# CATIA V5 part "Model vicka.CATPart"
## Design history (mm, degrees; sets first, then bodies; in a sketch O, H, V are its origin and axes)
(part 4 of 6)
    projected arc E6 centre (-2.5848, 1.1233) radius 51.9999 from (-41.5221, 35.5889) to (-51.4432, 18.9237) ccw from edge [face of Fillet16 | face of Pad13]
    line L1 (-57.9293, -19.8837) -> (-56.7487, -23.9144)
    length L1 = 4.2
    tangency: L1 E1
  Slot3: profile Sketch84, centre curve Sketch85
  Sketch86 on face of Slot3, origin (0, -14.9615, 15.7588), H (1, 0, 0), V (0, 0.7252, 0.6885)
    line L1 (-0.7, -58.186) -> (-0.7, -61.911)
    reference intersected line E1 (1.6, 68.0393) -> (1.6, -68.0393) from face of Pad32
    projected line E2 (1.6, -57.611) -> (-2.4, -58.611) from edge [face of Slot3 | face of Slot3]
    projected line E3 (1.6, -57.611) -> (-0.7, -58.186) from edge [face of Slot3 | face of Slot3]
    point P3 (1.6, -57.611)
    projected line E4 (1.6, -61.911) -> (1.6, -57.611) from edge [face of Pad32 | face of Slot3]
    point P5 (1.6, -61.911)
    point P6 (1.6, -57.611)
    projected line E5 (-2.4, -61.911) -> (1.6, -61.911) from edge [face of Slot3 | face of Slot3]
    projected line E6 (-0.7, -61.911) -> (1.6, -61.911) from edge [face of Slot3 | face of Slot3]
    point P8 (1.6, -61.911)
    distance E1 L1 = 2.3
    vertical: L1 V
    coincidence: P3 P6, P5 P8
  Sketch87 on face of Pad32, origin (1.6, 0, 0), H (0, 1, 0), V (0, 0, 1)
    projected arc E1 centre (-17.5753, -8.1503) radius 42.0001 from (-56.5286, -23.8555) to (-52.2283, -31.8816) ccw from edge [face of Fillet16 | face of Chamfer13]
    projected arc E2 centre (-17.6227, -8.0775) radius 42.0001 from (-52.2266, -31.8805) to (-45.9223, -39.112) ccw from edge [face of Fillet16 | end face of Pocket10]
    projected arc E3 centre (-17.6227, -8.0775) radius 42.0001 from (-52.1953, -31.9259) to (-45.9223, -39.112) ccw from edge [face of Fillet16 | end face of Pocket10]
    line L1 (-52.2283, -31.8816) -> (-52.1953, -31.9259)
    point P5 (-52.1953, -31.9259)
    length L1 = 0.0552
    coincidence: P5 E2
  Slot4: profile Sketch86, centre curve Sketch87
  Sketch88 on face of Slot3, origin (0, 5.9901, 23.455), H (1, 0, 0), V (0, -0.9689, 0.2474)
    projected line E1 (-2.4, 53.3276) -> (1.6, 53.3276) from edge [face of Slot3 | face of Slot3]
    projected line E2 (-2.4, 50.0276) -> (-2.4, 53.3276) from edge [face of Slot3 | face of Slot3]
    projected line E3 (1.6, 49.0276) -> (-2.4, 50.0276) from edge [face of Slot3 | face of Slot3]
    projected line E4 (1.6, 53.3276) -> (1.6, 49.0276) from edge [face of Slot3 | face of Pad32]
  Sketch89 on face of Pad32, origin (1.6, 0, 0), H (0, 1, 0), V (0, 0, 1)
    projected arc E1 centre (-2.5799, 1.1183) radius 51.507 from (-39.4324, 37.1026) to (-41.129, 35.2788) ccw from edge [face of Pad17 from Sketch31.A1 | face of Chamfer24]
    offset arc E2 centre (-2.5799, 1.1183) radius 52.007 from (-39.7901, 37.4519) to (-41.5032, 35.6104) ccw from edge [face of Pad17 from Sketch31.A1 | face of Chamfer24]
  Slot5: profile Sketch88, centre curve Sketch89
  Sketch90 on face of Slot5, origin (0, 7.0774, 23.0092), H (1, 0, 0), V (0, -0.9558, 0.294)
    projected line E1 (1.6, 49.0459) -> (1.6, 53.3459) from edge [face of Pad32 | face of Slot5]
    line L1 (1.6, 53.3459) -> (-6.4, 53.3459)
    point P3 (-6.4, 53.3459)
    line L2 (1.6, 49.0459) -> (-6.4, 53.3459)
    point P4 (-6.4, 53.3459)
    length L1 = 8
    horizontal: L1 H
    coincidence: P4 L1, L2 P3, P3 P4
  Sketch91 on face of Pad32, origin (1.6, 0, 0), H (0, 1, 0), V (0, 0, 1)
    projected arc E1 centre (-2.5829, 1.1221) radius 55.5117 from (-39.111, 42.9222) to (-42.5969, 39.5984) ccw from edge [face of Pad16 from Sketch30.E12 | end face of Pad17]
    line L1 (-42.5969, 39.5984) -> (-43.569, 38.5875)
    point P3 (-43.569, 38.5875)
    reference projected line E2 (-39.801, 37.4285) -> (-43.911, 38.6927) from edge [face of Pad32 | face of Slot5]
    distance P3 E2 = 0
    tangency: L1 E1
  Slot6: profile Sketch90, centre curve Sketch91
  Sketch92 on face of Pad32, origin (1.6, 0, 0), H (0, 1, 0), V (0, 0, 1)
    projected arc E1 centre (-2.5799, 1.1183) radius 51.507 from (-34.6189, 41.4479) to (-36.525, 39.8572) ccw from edge [face of Pad17 from Sketch31.A1 | face of Chamfer16]
    point P2 (-36.525, 39.8572)
    projected line E2 (-34.3922, 41.6269) -> (-34.6189, 41.4479) from edge [face of Pad12 | face of Chamfer16]
    projected line E4 (-32.9726, 42.7142) -> (-33.1688, 42.5588) from edge [face of Pad12 from Sketch20.L1 | face of Fillet15]
    projected arc E6 centre (-31.5752, 59.6552) radius 16.4993 from (-31.8705, 43.1586) to (-18.0387, 50.2219) ccw from edge [face of Pad12 from Sketch20.E32 | face of Fillet15]
    projected arc E7 centre (-8.752, 43.4382) radius 11.5005 from (-8.0778, 54.9189) to (-18.0387, 50.2219) ccw from edge [face of Pad12 from Sketch20.A1 | face of Fillet15]
    projected line E8 (13.3045, 53.6631) -> (-8.0778, 54.9189) from edge [face of Pad12 from Sketch20.E34 | face of Fillet15]
    projected arc E9 centre (7.4339, 25.3633) radius 28.9024 from (16.8502, 52.6887) to (13.3045, 53.6631) ccw from edge [face of Pad12 from Sketch20.E36 | face of Fillet15]
    projected arc E10 centre (7.4339, 25.3633) radius 28.9024 from (26.0505, 47.4714) to (20.4962, 51.1455) ccw from edge [face of Pad12 from Sketch20.E36 | face of Fillet15]
    projected arc E11 centre (7.4339, 25.3633) radius 28.9024 from (20.4962, 51.1455) to (18.2767, 52.1547) ccw from edge [face of Pad12 from Sketch20.E36 | face of Fillet15]
    projected arc E12 centre (40.4358, 56.1497) radius 16.6459 from (26.309, 47.3451) to (29.0781, 43.9805) ccw from edge [face of Chamfer6 | face of Fillet15]
    projected arc E13 centre (40.4358, 56.1497) radius 16.6459 from (27.5108, 45.6601) to (29.0781, 43.9805) ccw from edge [face of Chamfer6 | face of Fillet15]
    line L1 (26.0505, 47.4714) -> (27.5108, 45.6601)
    point P25 (27.5108, 45.6601)
    line L2 (18.2767, 52.1547) -> (16.8502, 52.6887)
    length L1 = 2.3266
    coincidence: P25 E12
  Plane6: type Normal, Curve Sketch92, RefPoint Sketch92.P2, Ratio 0
  Sketch93 on Plane6, origin (0, -0.9051, -0.7931), H (1, 0, 0), V (0, -0.659, 0.7521)
    line L1 (1.6, 54.0775) -> (1.6, 58.3775)
    line L2 (1.6, 58.3775) -> (-2.4, 58.3775)
    line L3 (-2.4, 58.3775) -> (-2.4, 55.0775)
    line L4 (-2.4, 55.0775) -> (1.6, 54.0775)
    reference projected line E1 (1.6, 52.57) -> (1.6, 60.7584) from edge [face of Pad32 | face of Pad10]
    reference projected line E2 (1.6, 58.3775) -> (-6.4, 58.3775) from edge [face of Slot6 | face of Slot6]
    distance L1 E1 = 0
    length L1 = 4.3
    length L3 = 3.3
    length L2 = 4
    distance L2 E2 = 0
    vertical: L1 V, L3 V
    horizontal: L2 H
  Slot7: profile Sketch93, centre curve Sketch92
  Chamfer28: length 4.9, angle 10, on edge [face of Slot5 | face of Slot5]
  Sketch94 on face of Pad32, origin (1.6, 0, 0), H (0, 1, 0), V (0, 0, 1)
    projected line E1 (-39.2656, 42.9849) -> (-39.3781, 43.1132) from edge [face of Slot7 | face of Pad32]
    projected line E2 (-39.2656, 42.9849) -> (-39.4426, 43.0566) from edge [face of Pad32 | face of Slot6]
    line L1 (-39.4426, 43.0566) -> (-39.3781, 43.1132)
    point P5 (-39.3781, 43.1132)
    length L1 = 0.0858
    coincidence: P5 E1
  Pocket31: profile Sketch94, direction (-1, 0, 0), length 4
  Sketch95 on face of Pad32, origin (1.6, 0, 0), H (0, 1, 0), V (0, 0, 1)
    projected arc E1 centre (-2.5799, 1.1183) radius 55.8361 from (-37.3069, 44.8414) to (-39.3781, 43.1132) ccw from edge [face of Pad32 | face of Slot7]
    projected arc E2 centre (-2.5799, 1.1183) radius 55.8361 from (-37.8798, 44.3802) to (-38.8031, 43.6101) ccw from edge [face of Pad32 | face of Slot7]
    point P2 (-39.3781, 43.1132)
    line L1 (-38.8031, 43.6101) -> (-37.4611, 39.7118)
    point P3 (-38.8184, 43.6551)
    point P4 (-37.4611, 39.7118)
    line L2 (-36.3174, 39.8416) -> (-37.8798, 44.3802)
    point P5 (-36.3174, 39.8416)
    point P6 (-37.6765, 44.2587)
    point P7 (-38.8031, 43.6101)
    point P8 (-38.8031, 43.6101)
    line L3 (-36.3174, 39.8416) -> (-36.215, 39.544)
    line L4 (-36.215, 39.544) -> (-37.4611, 39.7118)
    point P10 (-37.8798, 44.3802)
    point P11 (-37.8798, 44.3802)
    reference projected point E3 (-36.868, 40.2487) from vertex [face of Slot6 | face of Slot7 | face of Pad32]
    distance P3 E1 = 0.0442
    distance P3 P4 = 4.1703
    length L1 = 4.1228
    angle L1 L2 = 0
    distance P6 P7 = 1.3
    length L3 = 0.3147
    length L4 = 1.2574
    distance P5 P6 = 4.6215
    distance L1 P2 = 0.7054
    length L2 = 4.8
    distance P4 E3 = 0.8
    coincidence: L1 P7, E1 P8, L2 P10, E1 P11, P7 P8, P10 P11
    parallelism: L3 L2
  Pad33: profile Sketch95, direction (-1, 0, 0), up to the existing solid (limit type 2)
  Fillet36: radius 0.5, on edge [face of Pocket31 | face of Slot6]
  Fillet37: radius 0.5, on edge [face of Pad33 from Sketch95.L1 | face of Slot6]
  Sketch96 on face of Pad33, origin (1.6, 0, 0), H (0, 1, 0), V (0, 0, 1)
    projected arc E1 centre (-2.5799, 1.1183) radius 55.8578 from (-43.911, 38.6927) to (-45.6792, 36.6506) ccw from edge [face of Pad33 | face of Slot5]
    projected arc E2 centre (-2.5799, 1.1183) radius 55.8578 from (-43.911, 38.6927) to (-44.1709, 38.4048) ccw from edge [face of Pad33 | face of Slot5]
    point P1 (-43.911, 38.6927)
    projected line E3 (-42.9389, 39.7036) -> (-43.911, 38.6927) from edge [face of Pad33 | face of Slot6]
    projected line E4 (-43.2784, 39.3505) -> (-43.911, 38.6927) from edge [face of Pad33 | face of Slot6]
    point P4 (-43.911, 38.6927)
    projected line E5 (-40.3201, 36.8887) -> (-42.7571, 34.3543) from edge [face of Slot6 | face of Pad33]
    projected line E6 (-40.4271, 36.7774) -> (-41.3286, 35.8399) from edge [face of Slot6 | face of Pad33]
    point P7 (-45.0411, 37.4107)
    line L1 (-40.4271, 36.7774) -> (-43.2784, 39.3505)
    point P8 (-43.2784, 39.3505)
    point P9 (-40.4257, 36.7762)
    reference projected point E7 (-41.8454, 38.0573) from vertex [face of Slot5 | face of Chamfer28 | face of Slot6]
    line L2 (-41.3286, 35.8399) -> (-44.1709, 38.4048)
    point P10 (-41.3286, 35.8399)
    point P11 (-44.1709, 38.4048)
    point P12 (-40.4271, 36.7774)
    point P13 (-40.4271, 36.7774)
    distance E7 L1 = 0
    distance L1 L2 = 1.3
    length L2 = 3.8285
    distance P9 P8 = 3.8425
    coincidence: P8 E3, P10 E5, P11 E1, L1 P12, E5 P13, P1 P4, P12 P13
  Pad34: profile Sketch96, direction (-1, 0, 0), length 8
  Fillet38: radius 0.5, on edge [face of Slot6 | face of Slot6] (x3); edge [face of Slot6 | face of Pad34 from Sketch96.L1]; edge [face of Pad34 from Sketch96.L1 | face of Slot6]
  Sketch97 on face of Pad34, origin (1.6, 0, 0), H (0, 1, 0), V (0, 0, 1)
    projected arc E1 centre (32.0438, -10.8008) radius 27.8537 from (58.2467, -20.2473) to (59.3934, -16.076) ccw from edge [face of Chamfer3 | end face of Pad14]
    projected arc E2 centre (32.0438, -10.8008) radius 27.8537 from (58.6529, -19.0338) to (59.3934, -16.076) ccw from edge [face of Chamfer3 | end face of Pad14]
    point P2 (59.3934, -16.076)
    projected arc E3 centre (54.1383, -15.5258) radius 5.2838 from (59.3934, -16.076) to (58.8266, -13.0889) ccw from edge [face of Chamfer3 | end face of Pad14]
    point P3 (59.3934, -16.076)
    projected arc E4 centre (71.4411, -6.5318) radius 14.217 from (57.4963, -3.7635) to (58.8266, -13.0889) ccw from edge [face of Chamfer3 | end face of Pad14]
    projected arc E5 centre (44.449, -1.1758) radius 13.3015 from (57.4964, -3.7632) to (57.7347, -0.5287) ccw from edge [face of Chamfer3 | end face of Pad14]
    projected arc E6 centre (-26.1964, -18.2876) radius 85.7893 from (57.7347, -0.5287) to (33.9846, 42.8521) ccw from edge [face of Chamfer3 | end face of Pad14]
    line L1 (33.9846, 42.8521) -> (33.2896, 43.5711)
    point P11 (33.2896, 43.5711)
    reference projected arc E7 centre (40.4358, 56.1497) radius 12.3168 from (30.8763, 48.3831) to (32.0319, 47.1453) ccw from edge [face of Slot7 | face of Pad32]
    point P12 (58.6529, -19.0338)
    distance P11 E7 = 2.15
    length L1 = 1
    coincidence: P2 P3
  Plane7: type Normal, Curve Sketch97, RefPoint Sketch97.P12, Ratio 0
  Sketch98 on Plane7, origin (0, -0.2503, -0.8088), H (-1, 0, 0), V (0, -0.9553, 0.2956)
    line L1 (-1.6, -63.2013) -> (6.4, -63.2013)
    line L2 (6.4, -63.2013) -> (-1.6, -58.9013)
    line L3 (-1.6, -58.9013) -> (-1.6, -63.2013)
    reference intersected line E1 (-1.6, -71.42) -> (-1.6, 71.42) from face of Pad34
    distance L3 E1 = 0
    length L3 = 4.3
    length L1 = 8
    distance L1 H = 63.2013
    horizontal: L1 H
    vertical: L3 V
  Slot8: profile Sketch98, centre curve Sketch97
  Sketch99 on face of Slot7, origin (0, -6.3971, 5.9705), H (1, 0, 0), V (0, 0.6823, 0.7311)
    projected line E1 (1.6, 56.3219) -> (-2.4, 56.3219) from edge [face of Slot7 | face of Slot7]
    projected line E2 (1.6, 56.3219) -> (1.2703, 56.3219) from edge [face of Slot7 | face of Slot7]
    point P1 (1.6, 56.3219)
    projected line E3 (1.6, 53.76) -> (1.6, 56.3219) from edge [face of Pad34 | face of Slot7]
    point P4 (1.6, 56.3219)
    projected curve E4 from edge [face of Pocket14 from Sketch58.E5 | face of Slot7]
    line L1 (0.4039, 54.2321) -> (1.2703, 56.3219)
    point P7 (1.2703, 56.3219)
    reference projected line E5 (0.4039, 54.2321) -> (-0.314, 52.5004) from edge [face of Slot7 | face of Pocket16]
    angle L1 E5 = 180
    coincidence: P7 E1, P1 P4
  Pocket32: profile Sketch99, direction (0, 0.7311, -0.6823), length 3
  Sketch100 on face of Pad34, origin (1.6, 0, 0), H (0, 1, 0), V (0, 0, 1)
    projected line E1 (34.9087, 45.3925) -> (45.2512, 35.05) from edge [face of Pocket16 | face of Pad34]
    projected curve E2 from edge [face of Pocket14 from Sketch58.E5 | face of Pad34]
    projected curve E3 from edge [face of Pad34 | face of Pocket14 from Sketch58.E5]
    point P6 (33.7826, 45.5113)
    projected arc E4 centre (-26.1964, -18.2876) radius 87.3324 from (45.5459, 31.512) to (35.0808, 43.9383) ccw from edge [face of Slot8 | face of Pocket16]
    projected arc E5 centre (-26.1964, -18.2876) radius 87.3324 from (45.3346, 31.815) to (35.0808, 43.9383) ccw from edge [face of Slot8 | face of Pocket16]
    projected line E6 (34.3992, 44.6436) -> (35.0808, 43.9383) from edge [face of Slot8 | face of Pocket16]
    projected line E7 (33.6779, 45.6091) -> (34.2251, 45.0984) from edge [face of Pocket32 from Sketch99.E2 | face of Pocket16]
    projected line E8 (33.7826, 45.5113) -> (34.2251, 45.0984) from edge [face of Pocket32 from Sketch99.E2 | face of Pocket16]
    line L1 (34.3992, 44.6436) -> (34.2251, 45.0984)
    point P13 (34.3992, 44.6436)
    point P14 (45.3346, 31.815)
    point P15 (33.7826, 45.5113)
    length L1 = 0.487
    coincidence: P13 E6, E2 P14, E3 P15, P6 P15
  Pad35: profile Sketch100, direction (-1, 0, 0), up to the existing solid (limit type 2)
  Fill1: Boundary (edge [face of Pocket14 from Sketch58.E5 | face of Slot8]; edge [face of Slot8 | face of Pad35 from Sketch100.E2]; edge [face of Slot8 | face of Pocket16])
  Fill2: Boundary (edge [face of Pad35 from Sketch100.E3 | face of Pocket32]; edge [face of Pocket32 | face of Pocket16]; edge [face of Pocket32 | face of Pocket14 from Sketch58.E5])
  SewSurface1: SplitPlane Fill2
  SewSurface2: SplitPlane Fill1
  Sketch101 on face of Pad30, origin (-16.699, 4.8982, 4.8982), H (0.2815, 0.9596, 0), V (0.26, -0.0763, 0.9626)
  Sketch102 on face of Slot7, origin (0, -6.3971, 5.9705), H (1, 0, 0), V (0, 0.6823, 0.7311)
  Pocket33: profile Sketch102, direction (0, 0.7311, -0.6823), length 3.45
  Sketch103 on face of Pocket16, origin (-18.7311, 5.4943, 5.4943), H (0.2815, 0.9596, 0), V (0.26, -0.0763, 0.9626)
    projected line E1 (29.4824, 41.6823) -> (31.5877, 39.5448) from edge [face of Pocket16 | face of Pocket32 from Sketch99.E4]
    projected line E2 (29.4824, 41.6823) -> (28.1465, 40.3672) from edge [face of Pocket33 | face of Pocket16]
    projected line E3 (30.6493, 38.249) -> (33.3549, 40.6705) from edge [face of Slot8 | face of Pocket16]
    projected line E4 (31.5877, 39.5448) -> (33.211, 41.143) from edge [face of Pocket16 | end face of Pocket32]
    projected line E5 (33.3549, 40.6705) -> (33.211, 41.143) from edge [face of Pad35 from Sketch100.L1 | face of Pocket16]
    line L1 (30.6493, 38.249) -> (28.1465, 40.3672)
    point P11 (28.1465, 40.3672)
    length L1 = 3.2788
    coincidence: P11 E2
  Pocket34: profile Sketch103, direction (-0.9237, 0.2709, 0.2709), length 0.045
  Sketch104 on face of Pad35, origin (1.6, 0, 0), H (0, 1, 0), V (0, 0, 1)
    projected line E1 (34.2251, 45.0984) -> (34.3992, 44.6436) from edge [face of Pad35 from Sketch100.L1 | face of Pad35]
    line L1 (34.2251, 45.0984) -> (34.5351, 44.7902)
    line L2 (34.3992, 44.6436) -> (34.5351, 44.7902)
    angle L2 L1 = 92
    length L2 = 0.2
  Pocket35: profile Sketch104, direction (-1, 0, 0), length 1.045
  Sketch105 on face of Pad35, origin (1.6, 0, 0), H (0, 1, 0), V (0, 0, 1)
    projected line E1 (32.0319, 47.1453) -> (34.5541, 44.7913) from edge [face of Pocket33 | face of Pocket33]
    projected line E2 (34.2145, 45.1082) -> (34.5541, 44.7913) from edge [face of Pocket33 | face of Pocket33]
    point P2 (34.5541, 44.7913)
    projected line E3 (34.5541, 44.7913) -> (34.4078, 44.6346) from edge [face of Pocket33 | end face of Pocket33]
    point P3 (34.5541, 44.7913)
    projected line E4 (34.3992, 44.6436) -> (35.0808, 43.9383) from edge [face of Pad35 | face of Pad35]
    projected line E5 (34.3992, 44.6436) -> (34.4078, 44.6346) from edge [face of Pad35 | face of Pad35]
    line L1 (34.3992, 44.6436) -> (34.2145, 45.1082)
    point P7 (34.2145, 45.1082)
    length L1 = 0.5
    coincidence: P7 E1, P2 P3
  Pad36: profile Sketch105, direction (-1, 0, 0), up to the existing solid (limit type 2)
  Sketch106 on face of Pocket16, origin (-18.7311, 5.4943, 5.4943), H (0.2815, 0.9596, 0), V (0.26, -0.0763, 0.9626)
    line L1 (30.7758, 38.1148) -> (30.5655, 37.9079)
    point P1 (30.7758, 38.1148)
    line L2 (30.5655, 37.9079) -> (28.1465, 40.3672)
    point P3 (28.1465, 40.3672)
    point P4 (30.7758, 38.1148)
    projected line E1 (28.1465, 40.3672) -> (30.6493, 38.249) from edge [face of Pocket16 | face of Pocket34 from Sketch103.L1]
    point P5 (28.1465, 40.3672)
    projected line E2 (30.6525, 38.2519) -> (30.6493, 38.249) from edge [face of Pocket34 from Sketch103.E3 | face of Slot8]
    projected line E3 (30.6527, 38.2517) -> (30.7758, 38.1148) from edge [face of Slot8 | face of Pocket33]
    point P10 (30.7758, 38.1148)
    distance P1 P4 = 0
    distance P3 P5 = 0
    angle L1 L2 = 90
    length L1 = 0.295
    distance P1 P10 = 0
  Pocket36: profile Sketch106, direction (-0.9237, 0.2709, 0.2709), through (limit type 6)
  Draft4: Angle -3.5, Neutral face of Pocket16, PullDir face of Pocket16, SupportToDraft (end face of Pocket33; face of Pocket36 from Sketch106.L1)
  Fillet39: radius 3, on edge [face of Pocket33 | face of Slot8]
  Fillet40: radius 3, on edge [face of Pad36 from Sketch105.L1 | face of Pad35]
  Fillet41: radius 1, on edge [face of Pocket33 | face of Fillet40]
  Fillet42: radius 1.1, on edge [face of Pocket33 | face of Slot8]
  Fillet43: radius 0.75, on edge [face of Slot8 | face of Pocket36 from Sketch106.L1]
  Sketch107 on face of Pad36, origin (1.6, 0, 0), H (0, 1, 0), V (0, 0, 1)
    line L1 (33.2087, 46.047) -> (30.8894, 42.9692)
    line L2 (32.7188, 41.2429) -> (34.8949, 44.1306)
    projected line E1 (32.0319, 47.1453) -> (34.074, 45.2394) from edge [face of Pocket33 | face of Pad36]
    projected line E2 (33.2087, 46.047) -> (34.074, 45.2394) from edge [face of Pocket33 | face of Pad36]
    projected line E3 (29.4244, 44.3516) -> (32.0678, 41.8573) from edge [face of Pocket16 | face of Pocket36 from Sketch106.L2]
    projected line E4 (30.8894, 42.9692) -> (32.7188, 41.2429) from edge [face of Pocket16 | face of Pocket36 from Sketch106.L2]
    reference projected line E5 (32.5901, 32.7314) -> (38.0088, 38.1501) from Line1
    point P5 (32.7188, 41.2429)
    point P6 (30.8894, 42.9692)
    point P7 (33.2087, 46.047)
    projected arc E6 centre (33.3917, 44.5083) radius 1 from (34.2851, 44.9575) to (34.074, 45.2394) ccw from edge [face of Fillet41 | face of Pad36]
    projected arc E7 centre (36.9654, 46.3052) radius 3 from (34.2851, 44.9575) to (34.8083, 44.2202) ccw from edge [face of Pad36 | face of Fillet40]
    projected line E8 (34.8083, 44.2202) -> (35.0808, 43.9383) from edge [face of Pad35 | face of Pad36]
    projected line E9 (34.8083, 44.2202) -> (34.8949, 44.1306) from edge [face of Pad35 | face of Pad36]
    point P14 (34.8949, 44.1306)
    point P15 (34.8949, 44.1306)
    distance L1 L2 = 2.5
    angle L2 E5 = 8
    length L1 = 3.8538
    coincidence: E3 P5, E3 P6, E1 P7, L2 P14, E8 P15
  Pad37: profile Sketch107, direction (-1, 0, 0), up to the existing solid (limit type 2)
  Chamfer29: length 3.8, angle 26.2, on edge [face of Pad37 from Sketch107.E4 | face of Pad37]
  Sketch108 on face of Pocket16, origin (-18.7311, 5.4943, 5.4943), H (0.2815, 0.9596, 0), V (0.26, -0.0763, 0.9626)
    offset arc E1 centre (31.0473, 28.8138) radius 9.9633 from (30.7391, 18.8553) to (39.9051, 24.2523) ccw from edge [face of Pocket14 from Sketch58.E5 | face of Pocket16]
    offset arc E2 centre (31.0473, 28.8138) radius 9.9633 from (26.5278, 37.6931) to (30.7391, 18.8553) ccw from edge [face of Pocket15 | face of Pocket16]
    point P3 (26.5278, 37.6931)
    offset arc E3 centre (31.0473, 28.8138) radius 9.9633 from (28.2025, 38.3624) to (26.5278, 37.6931) ccw from edge [face of Pocket14 from Sketch58.E5 | face of Pocket16]
    point P6 (26.5278, 37.6931)
    arc A1 centre (31.0474, 28.8136) radius 9.9635 from (28.2025, 38.3624) to (29.7965, 38.6983) cw
    point P8 (29.228, 38.6096)
    arc A2 centre (31.0483, 28.8157) radius 9.9633 from (39.9051, 24.2523) to (40.5837, 25.9271) ccw
    point P10 (22.3411, 33.6585)
    point P11 (29.8518, 39.0314)
    projected line E4 (29.5646, 38.9363) -> (30.7209, 37.7499) from edge [face of Pad37 from Sketch107.E4 | face of Chamfer29]
    projected line E5 (29.5646, 38.9363) -> (29.7965, 38.6983) from edge [face of Pad37 from Sketch107.E4 | face of Chamfer29]
    point P12 (29.5646, 38.9363)
    projected arc E6 centre (31.0473, 28.8138) radius 12.9633 from (27.346, 41.2375) to (25.1669, 40.3667) ccw from edge [face of Pocket14 from Sketch58.E5 | face of Pocket16]
    point P14 (27.346, 41.2375)
    projected arc E7 centre (31.0473, 28.8138) radius 12.9633 from (25.1669, 40.3667) to (30.6462, 15.8567) ccw from edge [face of Pocket15 | face of Pocket16]
    projected arc E8 centre (31.0473, 28.8138) radius 12.9633 from (30.6462, 15.8567) to (42.5722, 22.8788) ccw from edge [face of Pocket14 from Sketch58.E5 | face of Pocket16]
    point P19 (42.5722, 22.8788)
    point P20 (29.7965, 38.6983)
    projected line E9 (28.1465, 40.3672) -> (29.559, 38.9311) from edge [face of Pocket16 | face of Pocket36 from Sketch106.L2]
    projected curve E10 from edge [face of Slot7 | face of Pocket16]
    projected curve E11 from edge [face of Slot8 | face of Pocket16]
    projected curve E12 from edge [face of Slot8 | face of Pocket16]
    point P25 (42.5722, 22.8788)
    point P27 (40.5837, 25.9271)
    projected line E13 (29.5646, 38.9363) -> (29.559, 38.9311) from edge [face of Pad37 from Sketch107.L1 | face of Pad37 from Sketch107.E4]
    point P28 (29.5646, 38.9363)
    radius A2 = 9.9633
    "Length" P25 P27 E11 = 3.6398
    radius A1 = 9.9635
    distance P20 P14 = 3.5288
    coincidence: P6 P3, A1 P8, P8 E3, A2 P10, P10 A1, P12 P28, P19 P25
  Pad38: profile Sketch108, direction (0.9237, -0.2709, -0.2709), length 10.2
  Sketch109 on zx-plane, origin (0, 0, 0), H (-1, 0, 0), V (0, 0, 1)
    line L1 (-1.6, 15) -> (-11.6, 15)
    line L2 (-11.6, 15) -> (-11.6, 45)
    line L3 (-11.6, 45) -> (-1.6, 45)
    line L4 (-1.6, 45) -> (-1.6, 15)
    reference projected line E1 (-1.6, -62.4295) -> (-1.6, 71.425) from edge [face of Pad1 from Sketch1.A1 | face of Pad37]
    distance L4 E1 = 0
    length L3 = 10
    length L2 = 30
    distance L1 H = 15
    horizontal: L1 H, L3 H
    vertical: L2 V, L4 V
  Pocket37: profile Sketch109, direction (0, -1, 0), through (limit type 6)
  Chamfer30: length 0.31, angle 85, on edge [face of Pocket14 from Sketch58.E5 | face of Slot7]
  Fillet44: radius 0.5, on edge [face of Chamfer30 | face of Slot7]; edge [face of Pad38 from Sketch108.E10 | face of Chamfer30]
  Fillet45: radius 1.1, on edge [face of Pad38 from Sketch108.E12 | face of Pad38 from Sketch108.E8]
  Sketch110 on face of Pad37, origin (1.6, 0, 0), H (0, 1, 0), V (0, 0, 1)
    line L1 (42.8242, 28.3998) -> (42.8242, 35.2204)
    point P1 (42.8242, 35.4644)
    line L2 (44.8242, 24.7293) -> (44.8242, 32.5359)
    projected arc E1 centre (42.6872, 26.7077) radius 1.0654 from (43.7295, 26.4869) to (43.5769, 27.2939) ccw from edge [face of Pad37 | face of Fillet45]
    point P2 (43.7295, 26.4869)
    point P3 (43.5769, 27.2939)
    projected arc E2 centre (-26.1964, -18.2876) radius 87.3324 from (59.2693, -0.3274) to (35.0808, 43.9383) ccw from edge [face of Pad37 | face of Slot8]
    projected arc E3 centre (-26.1964, -18.2876) radius 87.3324 from (44.8242, 32.5359) to (42.8242, 35.2204) ccw from edge [face of Pad37 | face of Slot8]
    projected arc E4 centre (-30.3056, -22.1814) radius 88.9182 from (43.5769, 27.2939) to (41.8242, 29.8159) ccw from edge [face of Pad37 | face of Pad38 from Sketch108.E12]
    projected arc E5 centre (-30.3056, -22.1814) radius 88.9182 from (43.5769, 27.2939) to (42.8242, 28.3998) ccw from edge [face of Pad37 | face of Pad38 from Sketch108.E12]
    point P6 (43.5769, 27.2939)
    point P7 (41.8242, 29.8159)
    projected arc E6 centre (-26.1964, -18.2876) radius 83.0324 from (54.9892, -0.8725) to (43.7295, 26.4869) ccw from edge [face of Slot8 | face of Pad37]
    projected arc E7 centre (-26.1964, -18.2876) radius 83.0324 from (44.8242, 24.7293) to (43.7295, 26.4869) ccw from edge [face of Slot8 | face of Pad37]
    point P9 (43.7295, 26.4869)
    point P10 (44.8242, 32.5359)
    point P11 (42.8242, 35.2204)
    point P12 (42.8242, 35.2204)
    point P13 (44.8242, 32.5359)
    point P14 (44.8242, 24.7293)
    point P15 (42.8242, 28.3998)
    point P16 (44.8242, 24.7293)
    distance P1 P7 H = 1
    distance L2 P7 = 3
    length L1 = 6.8207
    vertical: L1 V, L2 V
    coincidence: L2 P10, L1 P11, E2 P12, E2 P13, L2 P14, E4 P15, E6 P16, P2 P9, P3 P6, P10 P13, P11 P12, P14 P16
  Pad39: profile Sketch110, direction (-1, 0, 0), up to the existing solid (limit type 2)
  Sketch111 on face of Pad39, origin (1.6, 0, 0), H (0, 1, 0), V (0, 0, 1)
    line L1 (56.5341, -16.2847) -> (60.6532, -17.5591)
    line L2 (56.6395, -15.1658) -> (60.8868, -16.48)
    reference projected line E1 (56.0192, -18.2189) -> (60.1271, -19.4899) from edge [face of Pad34 | face of Slot8]
    projected arc E2 centre (32.0438, -10.8008) radius 29.3969 from (60.1271, -19.4899) to (60.9205, -16.3062) ccw from edge [face of Pad39 | face of Slot8]
    projected arc E3 centre (32.0438, -10.8008) radius 29.3969 from (60.6532, -17.5591) to (60.8868, -16.48) ccw from edge [face of Pad39 | face of Slot8]
    projected arc E4 centre (32.0438, -10.8008) radius 25.0969 from (56.0192, -18.2189) to (56.66, -15.689) ccw from edge [face of Slot8 | face of Pad39]
    projected arc E5 centre (32.0438, -10.8008) radius 25.0969 from (56.5341, -16.2847) to (56.66, -15.689) ccw from edge [face of Slot8 | face of Pad39]
    point P4 (56.66, -15.689)
    projected arc E6 centre (54.1383, -15.5258) radius 2.5269 from (56.66, -15.689) to (56.3805, -14.3604) ccw from edge [face of Slot8 | face of Pad39]
    projected arc E7 centre (54.1383, -15.5258) radius 2.5269 from (56.66, -15.689) to (56.6395, -15.1658) ccw from edge [face of Slot8 | face of Pad39]
    point P5 (56.66, -15.689)
    point P7 (60.8868, -16.48)
    point P8 (60.6532, -17.5591)
    point P9 (60.6532, -17.5591)
    point P10 (56.5341, -16.2847)
    point P11 (56.5341, -16.2847)
    point P12 (56.6395, -15.1658)
    distance L1 E1 = 2
    distance L1 L2 = 1.1
    coincidence: E2 P7, L1 P8, E2 P9, L1 P10, E4 P11, E6 P12, P4 P5, P8 P9, P10 P11
  Pad40: profile Sketch111, direction (-1, 0, 0), up to the existing solid (limit type 2)
  Sketch112 on face of Pad40, origin (1.6, 0, 0), H (0, 1, 0), V (0, 0, 1)
    line L1 (58.8974, -8.343) -> (54.5089, -7.7192)
    line L2 (58.7764, -7.0127) -> (54.4678, -6.4003)
    projected arc E1 centre (71.4411, -6.5318) radius 12.6738 from (59.0099, -4.064) to (60.1958, -12.3772) ccw from edge [face of Slot8 | face of Pad40]
    projected arc E2 centre (71.4411, -6.5318) radius 12.6738 from (58.7764, -7.0127) to (58.8974, -8.343) ccw from edge [face of Slot8 | face of Pad40]
    projected arc E3 centre (71.4411, -6.5318) radius 16.9738 from (54.7922, -3.2267) to (56.3805, -14.3604) ccw from edge [face of Pad40 | face of Slot8]
    projected arc E4 centre (71.4411, -6.5318) radius 16.9738 from (54.4678, -6.4003) to (54.5089, -7.7192) ccw from edge [face of Pad40 | face of Slot8]
    point P5 (58.7764, -7.0127)
    point P6 (58.8974, -8.343)
    point P7 (54.5089, -7.7192)
    point P8 (54.4678, -6.4003)
    reference projected arc E5 centre (69.5316, 12.3887) radius 4.4 from (65.7164, 14.5806) to (70.95, 8.2236) ccw from edge [face of Pocket7 from Sketch13.A1 | face of Pad40]
    distance P6 E5 = 18.9
    distance P7 E5 = 20.7
    distance L2 L1 = 1.3
    coincidence: E1 P5, E1 P6, E3 P7, E3 P8
  Pad41: profile Sketch112, direction (1, 0, 0), up to the existing solid (limit type 2)
  Sketch113 on face of Pad41, origin (1.6, 0, 0), H (0, 1, 0), V (0, 0, 1)
    line L1 (58.6538, 2.386) -> (52.9388, 6.8521)
    line L2 (59.1193, 0.3724) -> (53.5932, 4.6909)
    projected arc E1 centre (-26.1964, -18.2876) radius 87.3324 from (59.2693, -0.3274) to (44.8242, 32.5359) ccw from edge [face of Pad41 | face of Slot8]
    projected arc E2 centre (-26.1964, -18.2876) radius 87.3324 from (59.1193, 0.3724) to (58.6538, 2.386) ccw from edge [face of Pad41 | face of Slot8]
    projected arc E3 centre (-26.1964, -18.2876) radius 83.0324 from (54.9892, -0.8725) to (44.8242, 24.7293) ccw from edge [face of Slot8 | face of Pad41]
    projected arc E4 centre (-26.1964, -18.2876) radius 83.0324 from (53.5932, 4.6909) to (52.9388, 6.8521) ccw from edge [face of Slot8 | face of Pad41]
    point P5 (59.1193, 0.3724)
    point P6 (58.6538, 2.386)
    point P7 (53.5932, 4.6909)
    point P8 (52.9388, 6.8521)
    reference projected arc E5 centre (69.5316, 12.3887) radius 4.4 from (65.7164, 14.5806) to (70.95, 8.2236) ccw from edge [face of Pocket7 from Sketch13.A1 | face of Pad41]
    distance P5 E5 = 11.5
    distance P7 E5 = 13.3
    distance L1 L2 = 1.3
    coincidence: E1 P5, E1 P6, E3 P7, E3 P8
  Pad42: profile Sketch113, direction (-1, 0, 0), up to the existing solid (limit type 2)
  Draft5: Angle -10, Neutral face of Pad42, PullDir face of Pocket16, SupportToDraft (face of Pad38 from Sketch108.E2; face of Pad38 from Sketch108.E1; face of Pad38 from Sketch108.E3; face of Pad38 from Sketch108.A1)
  Fillet46: radius 1, on edge [face of Pad38 from Sketch108.E2 | face of Pad42]
  Fillet47: radius 0.1, on edge [face of Pad39 from Sketch110.L1 | face of Pad38 from Sketch108.E12]; edge [face of Pad38 from Sketch108.E12 | face of Fillet46]
  Sketch114 on face of Pad42, origin (1.6, 0, 0), H (0, 1, 0), V (0, 0, 1)
    line L1 (49.467, 15.9095) -> (53.4816, 17.4667)
    point P1 (49.467, 15.9095)
    point P2 (53.4816, 17.4667)
    line L2 (48.9212, 17.0922) -> (52.9396, 18.6508)
    reference projected point E1 (52.9388, 6.8521) from vertex [face of Pad42 from Sketch113.L1 | face of Slot8 | face of Pad42]
    projected arc E2 centre (-26.1964, -18.2876) radius 87.3324 from (58.6538, 2.386) to (44.8242, 32.5359) ccw from edge [face of Pad42 | face of Slot8]
    projected arc E3 centre (-26.1964, -18.2876) radius 87.3324 from (53.4816, 17.4667) to (52.9396, 18.6508) ccw from edge [face of Pad42 | face of Slot8]
    projected arc E4 centre (-26.1964, -18.2876) radius 83.0324 from (52.9388, 6.8521) to (44.8242, 24.7293) ccw from edge [face of Slot8 | face of Pad42]
    projected arc E5 centre (-26.1964, -18.2876) radius 83.0324 from (49.467, 15.9095) to (48.9212, 17.0922) ccw from edge [face of Slot8 | face of Pad42]
    reference projected point E6 (59.1193, 0.3724) from vertex [face of Pad42 from Sketch113.L2 | face of Slot8 | face of Pad42]
    distance P1 E1 = 9.7
    distance L2 L1 = 1.3
    distance P2 E6 = 18
  Pad43: profile Sketch114, direction (-1, 0, 0), up to the existing solid (limit type 2)
  Sketch115 on face of Pad43, origin (1.6, 0, 0), H (0, 1, 0), V (0, 0, 1)
    line L1 (24.1482, 48.9781) -> (27.8703, 51.5679)
    point P1 (28.2024, 51.6996)
    line L2 (22.9905, 49.7563) -> (26.7728, 52.388)
    projected arc E1 centre (7.4339, 25.3633) radius 33.2315 from (29.1677, 50.5023) to (19.8461, 56.1897) ccw from edge [face of Pad43 | face of Slot7]
    projected arc E2 centre (7.4339, 25.3633) radius 33.2315 from (27.8703, 51.5679) to (26.7728, 52.388) ccw from edge [face of Pad43 | face of Slot7]
    projected arc E3 centre (7.4339, 25.3633) radius 28.9315 from (26.0714, 47.4918) to (18.2873, 52.1818) ccw from edge [face of Slot7 | face of Pad43]
    projected arc E4 centre (7.4339, 25.3633) radius 28.9315 from (24.1482, 48.9781) to (22.9905, 49.7563) ccw from edge [face of Slot7 | face of Pad43]
    point P6 (27.8703, 51.5679)
    point P7 (27.8703, 51.5679)
    point P8 (24.1482, 48.9781)
    point P9 (24.1482, 48.9781)
    point P10 (22.9905, 49.7563)
    point P11 (26.7728, 52.388)
    reference projected line E5 (33.1359, 45.9505) -> (30.8894, 42.9692) from edge [face of Pad37 from Sketch107.L1 | face of Chamfer29]
    distance L2 L1 = 1.3
    length L1 = 4.5344
    distance E5 P8 = 9
    coincidence: L1 P6, E1 P7, L1 P8, E3 P9, E3 P10, E1 P11, P6 P7, P8 P9
  Pad44: profile Sketch115, direction (-1, 0, 0), up to the existing solid (limit type 2)
  Sketch116 on face of Pad44, origin (1.6, 0, 0), H (0, 1, 0), V (0, 0, 1)
    line L1 (17.5728, 52.4493) -> (17.5728, 57.0103)
    line L2 (16.2728, 52.9115) -> (16.2728, 57.3977)
    line L3 (7.6728, 54.023) -> (7.6728, 58.3305)
    line L4 (6.3728, 54.0994) -> (6.3728, 58.4068)
    line L5 (-2.2272, 54.6044) -> (-2.2272, 58.9119)
    line L6 (-3.5272, 54.6808) -> (-3.5272, 58.9882)
    projected line E1 (18.2873, 52.1818) -> (16.86, 52.7161) from edge [face of Slot7 | face of Pad44]
    projected line E2 (17.5728, 52.4493) -> (16.86, 52.7161) from edge [face of Slot7 | face of Pad44]
    point P2 (16.86, 52.7161)
    projected arc E3 centre (7.4339, 25.3633) radius 28.9315 from (16.86, 52.7161) to (13.3083, 53.6921) ccw from edge [face of Slot7 | face of Pad44]
    projected arc E4 centre (7.4339, 25.3633) radius 28.9315 from (16.86, 52.7161) to (16.2728, 52.9115) ccw from edge [face of Slot7 | face of Pad44]
    point P3 (16.86, 52.7161)
    projected line E5 (13.3083, 53.6921) -> (-8.0761, 54.9479) from edge [face of Slot7 | face of Pad44]
    projected line E6 (7.6728, 54.023) -> (6.3728, 54.0994) from edge [face of Slot7 | face of Pad44]
    projected line E7 (-2.2272, 54.6044) -> (-3.5272, 54.6808) from edge [face of Slot7 | face of Pad44]
    projected line E8 (13.863, 57.9669) -> (-7.824, 59.2405) from edge [face of Pad44 | face of Slot7]
    projected line E9 (7.6728, 58.3305) -> (6.3728, 58.4068) from edge [face of Pad44 | face of Slot7]
    projected line E10 (-2.2272, 58.9119) -> (-3.5272, 58.9882) from edge [face of Pad44 | face of Slot7]
    projected arc E11 centre (7.4339, 25.3633) radius 33.2315 from (18.3164, 56.7624) to (13.863, 57.9669) ccw from edge [face of Pad44 | face of Slot7]
    projected arc E12 centre (7.4339, 25.3633) radius 33.2315 from (17.5728, 57.0103) to (16.2728, 57.3977) ccw from edge [face of Pad44 | face of Slot7]
    reference projected point E13 (26.7728, 52.388) from vertex [face of Pad44 from Sketch115.L2 | face of Slot7 | face of Pad44]
    point P12 (16.2728, 52.9115)
    point P13 (17.5728, 57.0103)
    point P14 (16.2728, 57.3977)
    point P15 (17.5728, 57.0103)
    point P16 (7.6728, 58.3305)
    point P18 (6.3728, 54.0994)
    point P19 (-2.2272, 54.6044)
    point P20 (6.3728, 58.4068)
    point P21 (7.6728, 58.3305)
    point P22 (-2.2272, 58.9119)
    point P23 (-2.2272, 58.9119)
    point P24 (-2.2272, 54.6044)
    point P25 (-3.5272, 54.6808)
    point P26 (-3.5272, 58.9882)
    point P27 (-3.5272, 58.9882)
    distance L1 E13 = 9.2
    distance L4 L3 = 1.3
    distance L5 L4 = 8.6
    distance L6 L5 = 1.3
    distance L2 L1 = 1.3
    distance L2 L3 = 8.6
    vertical: L1 V, L2 V, L3 V, L4 V, L5 V, L6 V
    coincidence: E3 P12, L1 P13, E11 P14, E11 P15, L3 P16, E5 P18, L5 P19, E8 P20, E8 P21, L5 P22, E8 P23, E5 P24, E5 P25, L6 P26, E8 P27, P2 P3, P13 P15, P16 P21, P19 P24, P22 P23, P26 P27
  Pad45: profile Sketch116, direction (-1, 0, 0), up to the existing solid (limit type 2)
  Sketch117 on face of Pad45, origin (1.6, 0, 0), H (0, 1, 0), V (0, 0, 1)
    line L1 (-15.5272, 52.7671) -> (-18.9272, 55.5643)
    line L2 (-16.5532, 51.9278) -> (-19.8974, 54.679)
    line L3 (-22.6539, 45.8105) -> (-25.3221, 49.2144)
    line L4 (-23.7838, 45.1446) -> (-26.4908, 48.5981)
    line L5 (-46.3493, 29.1908) -> (-51.111, 28.7733)
    line L6 (-47.2042, 27.8109) -> (-51.8671, 27.4021)
    line L7 (-50.9931, 20.0905) -> (-54.9508, 20.6707)
    line L8 (-51.4627, 18.8454) -> (-55.355, 19.416)
    line L9 (-52.9612, 11.0592) -> (-56.8321, 12.6588)
    line L10 (-53.0787, 9.7011) -> (-56.7054, 11.1998)
    line L11 (-54.1572, 4.5203) -> (-57.1074, 8.1199)
    line L12 (-54.6494, 3.07) -> (-57.4778, 6.521)
    projected arc E1 centre (-8.752, 43.4382) radius 11.5296 from (-8.0761, 54.9479) to (-18.0624, 50.2388) ccw from edge [face of Slot7 | face of Pad45]
    projected arc E2 centre (-8.752, 43.4382) radius 11.5296 from (-15.5272, 52.7671) to (-16.5532, 51.9278) ccw from edge [face of Slot7 | face of Pad45]
    projected arc E3 centre (-31.5752, 59.6552) radius 16.4702 from (-31.87, 43.1877) to (-18.0624, 50.2388) ccw from edge [face of Pad45 | face of Slot7]
    projected arc E4 centre (-31.5752, 59.6552) radius 16.4702 from (-23.7838, 45.1446) to (-22.6539, 45.8105) ccw from edge [face of Pad45 | face of Slot7]
    projected arc E5 centre (-31.5752, 59.6552) radius 12.1702 from (-31.793, 47.487) to (-21.55, 52.7554) ccw from edge [face of Slot7 | face of Pad45]
    projected arc E6 centre (-31.5752, 59.6552) radius 12.1702 from (-26.4908, 48.5981) to (-25.3221, 49.2144) ccw from edge [face of Slot7 | face of Pad45]
    projected arc E7 centre (-8.752, 43.4382) radius 15.8296 from (-7.824, 59.2405) to (-21.5494, 52.755) ccw from edge [face of Pad45 | face of Slot7]
    projected arc E8 centre (-8.752, 43.4382) radius 15.8296 from (-18.9272, 55.5643) to (-19.8974, 54.679) ccw from edge [face of Pad45 | face of Slot7]
    point P9 (-51.5985, 18.8407)
    projected arc E9 centre (-80.9165, 12.7936) radius 28.0091 from (-55.5853, 0.8421) to (-52.929, 13.8923) ccw from edge [face of Pad45 | face of Slot3]
    point P12 (-18.9272, 55.5643)
    point P13 (-19.8974, 54.679)
    point P15 (-15.5272, 52.7671)
    reference projected line E10 (-3.5272, 58.9882) -> (-3.5272, 54.6808) from edge [face of Pad45 from Sketch116.L6 | face of Pad45]
    point P16 (-22.6539, 45.8105)
    point P17 (-25.3221, 49.2144)
    point P18 (-26.4908, 48.5981)
    point P20 (-22.6539, 45.8105)
    point P21 (-25.3221, 49.2144)
    point P22 (-26.4908, 48.5981)
    point P23 (-46.3493, 29.1908)
    point P24 (-47.2042, 27.8109)
    point P25 (-51.9396, 27.2247)
    point P26 (-51.111, 28.7733)
    point P27 (-54.9057, 20.664)
    point P28 (-49.8099, 19.8596)
    point P30 (-52.9612, 11.0592)
    reference projected line E11 (-44.1709, 38.4048) -> (-41.3286, 35.8399) from edge [face of Pad34 from Sketch96.L2 | face of Pad45]
    point P32 (-50.9931, 20.0905)
    point P34 (-55.355, 19.416)
    projected arc E12 centre (-45.939, 14.1611) radius 10.9962 from (-56.9293, 14.5211) to (-56.6743, 11.7798) ccw from edge [face of Pad45 | face of Slot3]
    projected arc E13 centre (-45.939, 14.1611) radius 10.9962 from (-56.8321, 12.6588) to (-56.6743, 11.7798) ccw from edge [face of Pad45 | face of Slot3]
    point P37 (-56.8321, 12.6588)
    projected arc E14 centre (-80.9165, 12.7936) radius 24.2635 from (-61.1612, -1.2934) to (-56.6742, 11.7796) ccw from edge [face of Slot3 | face of Pad45]
    projected arc E15 centre (-80.9165, 12.7936) radius 24.2635 from (-57.4778, 6.521) to (-57.1074, 8.1199) ccw from edge [face of Slot3 | face of Pad45]
    projected arc E16 centre (-80.9165, 12.7936) radius 24.2635 from (-56.7054, 11.1998) to (-56.6742, 11.7796) ccw from edge [face of Slot3 | face of Pad45]
    point P41 (-54.1572, 4.5203)
    point P44 (-57.1074, 8.1199)
    projected arc E17 centre (-80.9165, 12.7936) radius 28.0091 from (-55.5853, 0.8421) to (-52.929, 13.8923) ccw from edge [face of Pad45 | face of Slot3]
    projected arc E18 centre (-80.9165, 12.7936) radius 28.0091 from (-54.6494, 3.07) to (-54.1572, 4.5203) ccw from edge [face of Pad45 | face of Slot3]
    projected arc E19 centre (-80.9165, 12.7936) radius 28.0091 from (-53.0787, 9.7011) to (-52.9612, 11.0592) ccw from edge [face of Pad45 | face of Slot3]
    projected arc E20 centre (-2.5848, 1.1233) radius 51.9915 from (-43.1291, 33.6699) to (-51.4338, 18.9249) ccw from edge [face of Slot3 | face of Pad45]
    projected arc E21 centre (-2.5848, 1.1233) radius 51.9915 from (-46.3493, 29.1908) to (-47.2042, 27.8109) ccw from edge [face of Slot3 | face of Pad45]
    projected arc E22 centre (-2.5848, 1.1233) radius 51.9915 from (-50.9931, 20.0905) to (-51.4338, 18.9249) ccw from edge [face of Slot3 | face of Pad45]
    projected arc E23 centre (35.0097, -12.5726) radius 92.0031 from (-51.4338, 18.9249) to (-51.741, 18.0685) ccw from edge [face of Slot3 | face of Pad45]
    projected arc E24 centre (35.0097, -12.5726) radius 92.0031 from (-51.4338, 18.9249) to (-51.4627, 18.8454) ccw from edge [face of Slot3 | face of Pad45]
    projected arc E25 centre (-2.5848, 1.1233) radius 55.8508 from (-45.6792, 36.6506) to (-55.7001, 18.3883) ccw from edge [face of Pad45 | face of Slot3]
    projected arc E26 centre (-2.5848, 1.1233) radius 55.8508 from (-51.111, 28.7733) to (-51.8671, 27.4021) ccw from edge [face of Pad45 | face of Slot3]
    line L13 (-54.9508, 20.6707) -> (-55.355, 19.416)
    reference projected point E27 (-45.939, 14.1611) from edge
    distance P12 E10 = 15.4
    distance P15 E10 = 12
    distance L2 L1 = 1.3
    distance L3 L4 = 1.3
    distance P17 P13 = 7.7
    distance P16 L2 = 8.6
    distance P26 E11 = 11.8
    distance L6 L5 = 1.3
    distance P27 P25 = 7.2
    distance L8 L7 = 1.3
    distance L10 L9 = 1.3
    distance P37 L8 = 6.9
    distance L12 L11 = 1.3
    distance P44 L10 = 3
    distance P41 L10 = 5.2
    distance P30 P9 = 7.9
    distance P23 E11 = 8.3
    distance P24 P32 = 8.6
    distance P27 E25 = 0
    distance P34 E25 = 0
    length L13 = 1.3181
    length L7 = 4
    distance L9 E27 = 5.5487
    coincidence: E7 P12, E1 P15, L3 P16, L3 P17, L4 P18, E3 P20, E5 P21, E5 P22, L7 P27, E12 P37, P16 P20, P17 P21, P18 P22
  Pad46: profile Sketch117, direction (-1, 0, 0), up to the existing solid (limit type 2)
  Chamfer31: length 1.7, second length 10, on edge [face of Slot3 | face of Slot4]
  Sketch118 on face of Pad46, origin (1.6, 0, 0), H (0, 1, 0), V (0, 0, 1)
    line L1 (-48.9815, -36.3431) -> (-51.7887, -39.2395)
    line L2 (-52.6536, -38.264) -> (-49.8398, -35.3607)
    projected arc E1 centre (-17.6227, -8.0775) radius 42.2175 from (-52.3721, -32.0524) to (-46.0918, -39.2516) ccw from edge [face of Slot4 | face of Pad46]
    projected arc E2 centre (-17.6227, -8.0775) radius 42.2175 from (-49.8398, -35.3607) to (-48.9815, -36.3431) ccw from edge [face of Slot4 | face of Pad46]
    point P2 (-46.0918, -39.2516)
    projected arc E3 centre (-17.6227, -8.0775) radius 46.2427 from (-55.9851, -33.8982) to (-47.6191, -43.2712) ccw from edge [face of Pad46 | face of Slot4]
    projected arc E4 centre (-17.6227, -8.0775) radius 46.2427 from (-52.6536, -38.264) to (-51.7887, -39.2395) ccw from edge [face of Pad46 | face of Slot4]
    point P4 (-47.6191, -43.2712)
    point P5 (-48.9815, -36.3431)
    point P6 (-51.7887, -39.2395)
    point P7 (-52.6536, -38.264)
    point P8 (-49.8398, -35.3607)
    point P9 (-52.6536, -38.264)
    point P10 (-51.7887, -39.2395)
    line L3 (-56.2838, -25.0015) -> (-59.6603, -27.3138)
    line L4 (-56.7829, -23.7676) -> (-60.1026, -26.0411)
    projected arc E5 centre (-17.5753, -8.1503) radius 42.2175 from (-56.7418, -23.9078) to (-52.4053, -32.0079) ccw from edge [face of Slot4 | face of Pad46]
    projected arc E6 centre (-17.5753, -8.1503) radius 42.2175 from (-56.7418, -23.9078) to (-56.2838, -25.0015) ccw from edge [face of Slot4 | face of Pad46]
    point P11 (-56.7418, -23.9078)
    projected line E7 (-57.9224, -19.8772) -> (-56.7418, -23.9078) from edge [face of Slot3 | face of Pad46]
    projected line E8 (-56.7829, -23.7676) -> (-56.7418, -23.9078) from edge [face of Slot3 | face of Pad46]
    point P14 (-56.7418, -23.9078)
    projected line E9 (-61.0408, -22.8379) -> (-59.8602, -26.8685) from edge [face of Pad46 | face of Slot3]
    projected line E10 (-60.1026, -26.0411) -> (-59.8602, -26.8685) from edge [face of Pad46 | face of Slot3]
    point P16 (-59.8602, -26.8685)
    projected arc E11 centre (-17.5753, -8.1503) radius 46.2427 from (-59.8602, -26.8685) to (-55.9997, -33.8787) ccw from edge [face of Pad46 | face of Slot4]
    projected arc E12 centre (-17.5753, -8.1503) radius 46.2427 from (-59.8602, -26.8685) to (-59.6603, -27.3138) ccw from edge [face of Pad46 | face of Slot4]
    point P17 (-59.8602, -26.8685)
    point P19 (-56.2838, -25.0015)
    point P20 (-56.7829, -23.7676)
    point P21 (-60.1026, -26.0411)
    point P22 (-59.6603, -27.3138)
    line L5 (-59.228, -13.5563) -> (-63.1015, -14.0092)
    line L6 (-59.3151, -12.2576) -> (-63.1983, -12.7116)
    projected arc E13 centre (-37.3365, -11.4347) radius 21.994 from (-55.5853, 0.8421) to (-59.0194, -15.121) ccw from edge [face of Slot3 | face of Pad46]
    projected arc E14 centre (-37.3365, -11.4347) radius 21.994 from (-59.3151, -12.2576) to (-59.228, -13.5563) ccw from edge [face of Slot3 | face of Pad46]
    projected arc E15 centre (-37.3365, -11.4347) radius 25.8933 from (-61.1612, -1.2934) to (-62.4604, -17.6997) ccw from edge [face of Pad46 | face of Slot3]
    projected arc E16 centre (-37.3365, -11.4347) radius 25.8933 from (-63.1983, -12.7116) to (-63.1015, -14.0092) ccw from edge [face of Pad46 | face of Slot3]
    point P27 (-59.3151, -12.2576)
    point P28 (-59.228, -13.5563)
    point P29 (-59.228, -13.5563)
    point P30 (-63.1015, -14.0092)
    point P31 (-63.1015, -14.0092)
    point P32 (-63.1983, -12.7116)
    distance P5 P2 = 4.1
    distance P6 P4 = 5.8
    distance L2 L1 = 1.3
    distance P19 P8 = 12.2
    distance L3 L4 = 1.3
    distance P22 P7 = 13
    distance P21 P31 = 12.4
    distance P28 P20 = 10.5
    distance L6 L5 = 1.3
    coincidence: E1 P5, L1 P6, L2 P7, E1 P8, E3 P9, E3 P10, E5 P19, E7 P20, E9 P21, E11 P22, E13 P27, L5 P28, E13 P29, L5 P30, E15 P31, E15 P32, P6 P10, P7 P9, P11 P14, P16 P17, P28 P29, P30 P31
  Pad47: profile Sketch118, direction (-1, 0, 0), up to the existing solid (limit type 2)
  Sketch119 on face of Pad47, origin (1.6, 0, 0), H (0, 1, 0), V (0, 0, 1)
    line L1 (-63.1114, 16.9779) -> (-61.2757, 20.8474)
    point P1 (-61.2757, 20.8474)
    line L2 (-61.2757, 20.8474) -> (-65.1735, 18.7249)
    offset circle E1 centre (-68.2522, 13.0002) radius 6.5 from edge [face of Pad47 | face of Hole9]
    offset arc E2 centre (-68.2522, 13.0002) radius 6.5 from (-63.1114, 16.9779) to (-65.1735, 18.7249) ccw from edge [face of Pad47 | face of Hole9]
    reference projected circle E3 centre (0, 0) radius 71.425 from edge [face of Pad1 from Sketch1.A1 | face of Pad47]
    point P2 (-65.1735, 18.7249)
    point P3 (-63.1114, 16.9779)
    point P4 (-65.1735, 18.7249)
    point P5 (-63.1114, 16.9779)
    offset circle E4 centre (-35.5625, 59.6882) radius 6.4 from edge [face of Pad47 | face of Hole8]
    offset arc E5 centre (-35.5625, 59.6882) radius 6.4 from (-33.1655, 53.754) to (-30.4107, 55.8909) ccw from edge [face of Pad47 | face of Hole8]
    offset arc E6 centre (-35.5625, 59.6882) radius 6.4 from (-38.6712, 54.0939) to (-34.2607, 53.422) ccw from edge [face of Pad47 | face of Hole8]
    offset arc E7 centre (-35.5625, 59.6882) radius 6.4 from (-29.8107, 56.8816) to (-29.5056, 61.7557) ccw from edge [face of Pad47 | face of Hole8]
    point P6 (-38.5897, 48.5938)
    line L3 (-38.5897, 48.5938) -> (-34.2109, 50.056)
    point P7 (-33.8477, 50.1773)
    arc A1 centre (-40.2288, 68.0778) radius 19 from (-33.1167, 50.4591) to (-26.462, 54.9829) ccw
    point P9 (-25.8274, 55.9051)
    line L4 (-25.628, 55.9198) -> (-22.1725, 60.0696)
    point P10 (-22.1725, 60.0696)
    reference projected arc E8 centre (-35.5625, 59.6882) radius 6 from (-31.5, 64.1037) to (-41.3794, 58.2175) ccw from edge [face of Pad47 | face of Pad10]
    reference projected point E9 (-42.3563, 57.5107) from vertex [face of Fillet6 | face of Pad1 from Sketch1.A1 | face of Pad37]
    reference projected point E10 (-35.5625, 59.6882) from Sketch44.P5
    line L5 (-38.5897, 48.5938) -> (-38.6712, 54.0939)
    point P11 (-38.6712, 54.0939)
    reference projected arc E11 centre (-43.5423, 59.121) radius 2 from (-42.3563, 57.5107) to (-41.5474, 59.2628) ccw from edge [face of Fillet6 | face of Pad37]
    line L6 (-34.2109, 50.056) -> (-34.2607, 53.422)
